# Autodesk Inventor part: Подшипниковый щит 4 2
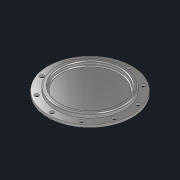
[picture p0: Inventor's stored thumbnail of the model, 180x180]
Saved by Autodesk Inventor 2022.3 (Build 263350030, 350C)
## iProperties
Created: 2022-08
Part Number: Подшипниковый щит 4 2
Material: Сталь 40ХНМА
Document SubType Name: Modeling
Designer: Карташов
Density: 7.85 g/cm^3
Appearance: С умеренной полировкой
Author: Карташов
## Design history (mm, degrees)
sketch "Эскиз1"
  geometry: L1 (0, 0)-(0, 34.001); L2 (50, -5)-(80, -5); L3 (80, -5)-(80, 0); L4 (80, 0)-(65, 0); L5 (65, 0)-(65, 6); L6 (63, 8)-(59, 8); L7 (57, 6)-(57, 2); L8 (55, 0)-(0, 0); L9 (50, -5)-(48, -7); L10 (48, -7)-(0, -7); L11 (0, -7)-(0, 0); A1 r 2 centre (55, 2) between (55, 0) and (57, 2); A2 r 2 centre (63, 6) between (65, 6) and (63, 8); A3 r 2 centre (59, 6) between (59, 8) and (57, 6); 4 further points
  constraints: 22 end point, 6 point on circle, 6 tangent, 5 horizontal, 4 point on line, 3 centre point, 3 vertical, 2 midpoint, 2 perpendicular
  dimensions: "d0" = 130 diameter of L5 point (0, 17); "d1" = 160 diameter of L3 L1; "d4" = 5 distance of L2.end L3.end; "d5" = 8 distance between parallel lines of L8 L6; "d6" = 8 distance of point (65, 8) point (57, 8); "d7" = 2 radius of A1; "d21" = 2 horizontal distance of L2.start L9.end; "d22" = 2 horizontal distance of L2.start L9.end; "d23" = 100 diameter of L2.start L1; "d24" = 2 radius of A2; "d25" = 2 radius of A3 (derived); "d26" = 15 distance from line of point (61, 8) L10
revolve "Вращение1" sketch "Эскиз1" stored, may be unused: angle "d9" = 90 deg
sketch "Эскиз2"
  geometry: C1 r 65 at (0, 0) reference; C2 r 80 at (0, 0) reference; 2 further points
  constraints: 1 vertical alignment
  dimensions: "d10" = 72.5 distance of point (0, 0) point (0, -72.5)
  node "Спроецированная петля1"
sketch "Эскиз3"
  geometry: 2 further points
hole "Отверстие1" sketch "Эскиз3" at (0, 72.5) diameter "d11" = 8; stored, may be unused: countersink angle "d15" = 90 deg, drill point angle "d17" = 0 deg; dims "d12" = 6, "d13" = 13, "d14" = 1, "d16" = 22.5
pattern_circular "Круговой массив1" dims angle "d19" = 360 deg
node "Твердое тело1"
